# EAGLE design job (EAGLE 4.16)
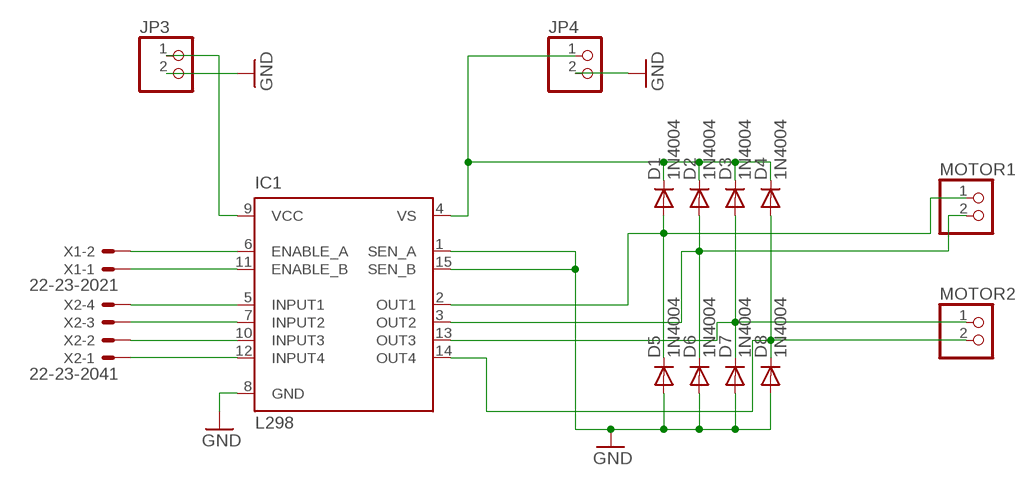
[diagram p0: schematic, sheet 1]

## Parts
D1  1N4004  [DO41-10]
D2  1N4004  [DO41-10]
D3  1N4004  [DO41-10]
D4  1N4004  [DO41-10]
D5  1N4004  [DO41-10]
D6  1N4004  [DO41-10]
D7  1N4004  [DO41-10]
D8  1N4004  [DO41-10]
IC1  L298  [MULTIWATT-15]
JP3  PINHD-1X2  [1X02]
JP4  PINHD-1X2  [1X02]
MOTOR1  PINHD-1X2  [1X02]
MOTOR2  PINHD-1X2  [1X02]
X1  22-23-2021  [22-23-2021]
X2  22-23-2041  [22-23-2041]

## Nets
GND: D5.A D6.A D7.A D8.A IC1.1(SEN_A) IC1.8(GND) IC1.15(SEN_B) JP3.2 JP4.2
N$1: IC1.9(VCC) JP3.1
N$2: D1.A D5.C IC1.2(OUT1) MOTOR1.1
N$3: D2.A D6.C IC1.3(OUT2) MOTOR1.2
N$4: D3.A D7.C IC1.13(OUT3) MOTOR2.1
N$5: D4.A D8.C IC1.14(OUT4) MOTOR2.2
N$6: D1.C D2.C D3.C D4.C IC1.4(VS) JP4.1
N$13: IC1.5(INPUT1) X2.4
N$14: IC1.7(INPUT2) X2.3
N$15: IC1.10(INPUT3) X2.2
N$16: IC1.12(INPUT4) X2.1
N$17: IC1.6(ENABLE_A) X1.2
N$18: IC1.11(ENABLE_B) X1.1

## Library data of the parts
D1-D8 = diode:1N4004: DIODE
IC1 = st-microelectronics:L298: DUAL FULL-BRIDGE DRIVER
JP3 JP4 MOTOR1 MOTOR2 = pinhead:PINHD-1X2: PIN HEADER
X1 = con-molex:22-23-2021: .100" (2.54mm) Center Header - 2 Pin
X2 = con-molex:22-23-2041: .100" (2.54mm) Center Header - 4 Pin

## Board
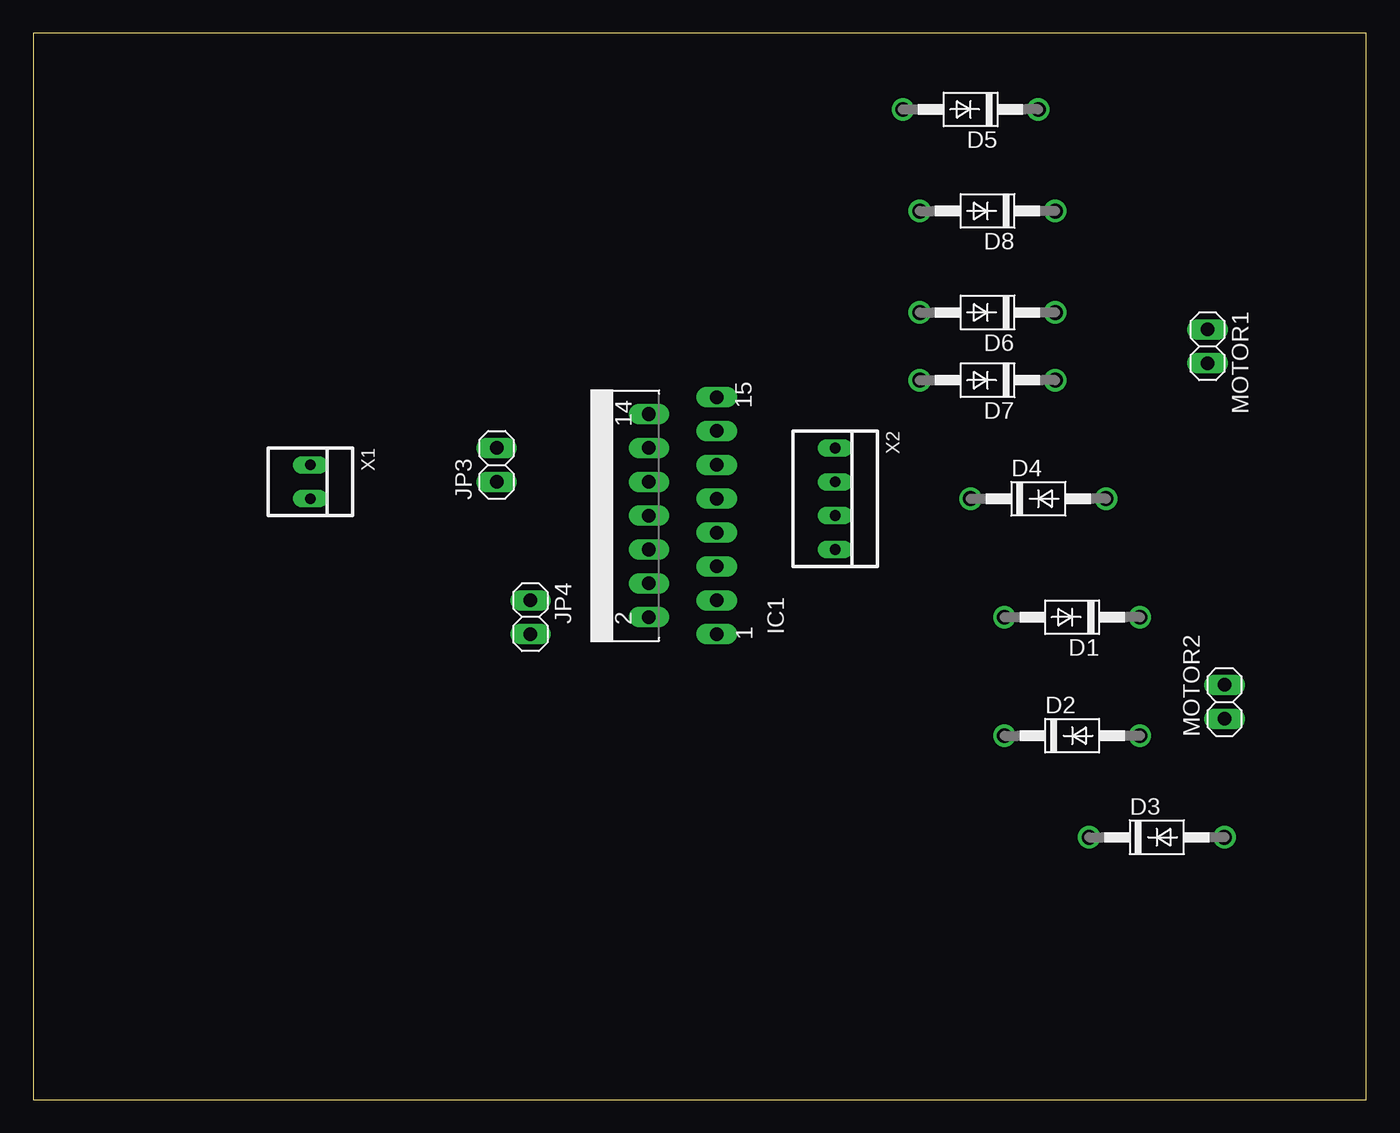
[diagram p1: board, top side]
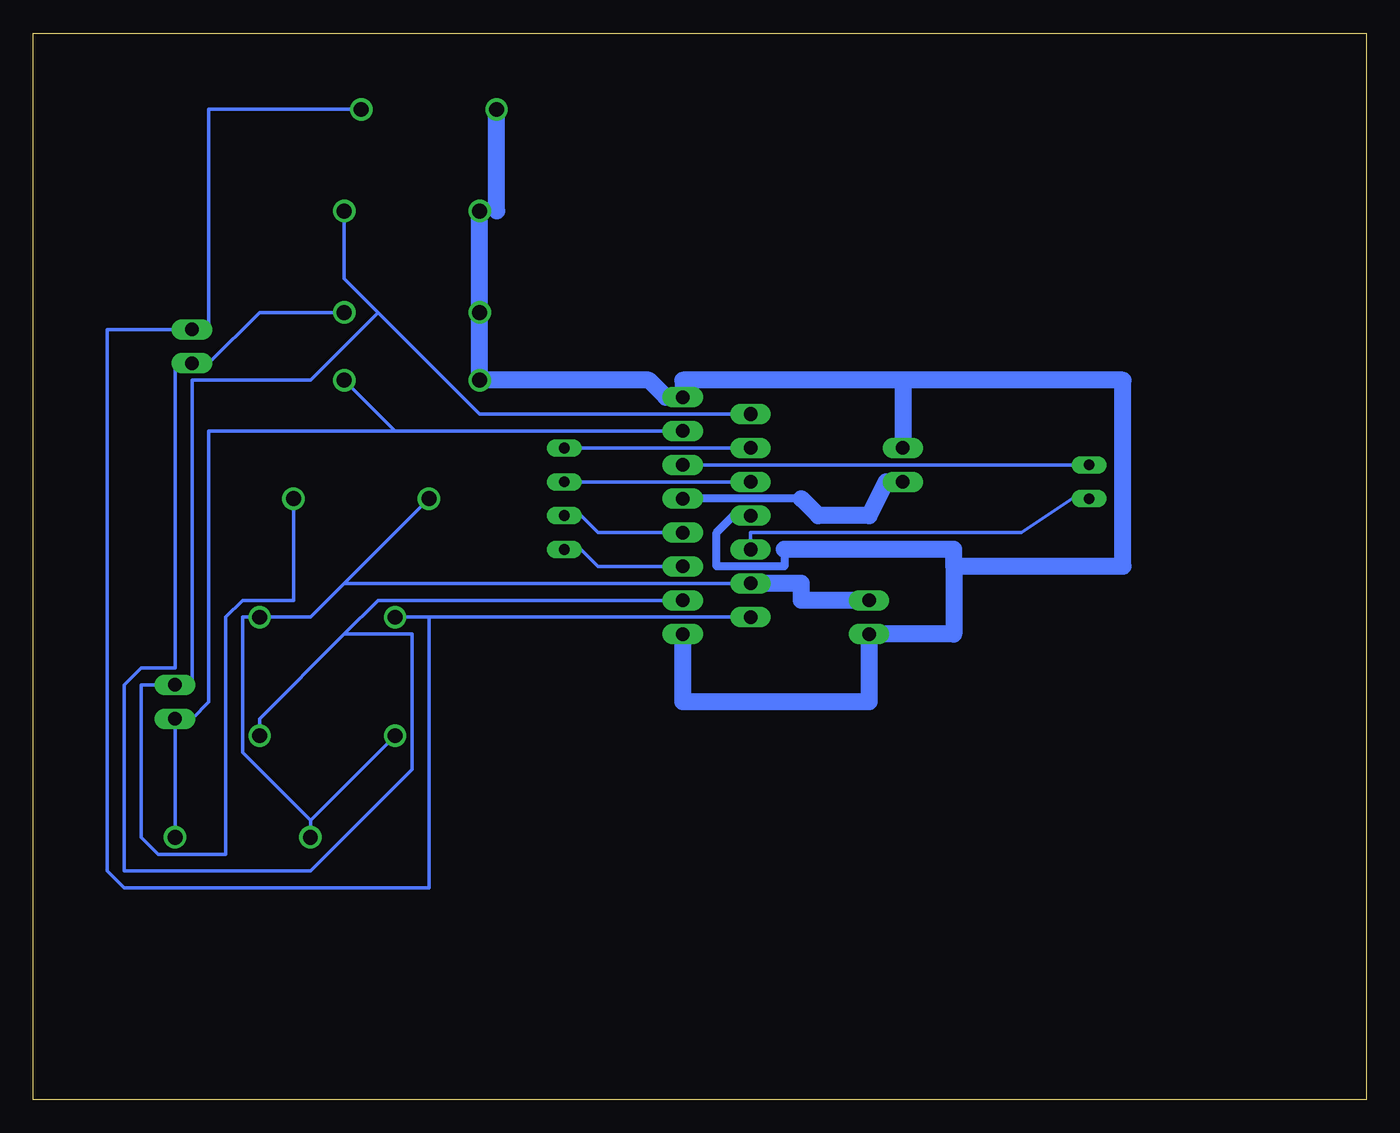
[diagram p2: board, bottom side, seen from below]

Size 100 x 80 mm. Coordinates in mm from the lower left corner, seen from the top.
Outline: 0,0 100,0 100,80 0,80 0,0
Copper layers (1*16): Top 0.035mm / dielectric 1.5mm / Bottom 0.035mm
Design rules "default": minimum track width 10mil, minimum drill 24mil, track to track 8mil, track to pad 8mil, pad to pad 8mil, via to via 8mil, smd to smd 8mil, copper to edge 40mil, drill to drill 8mil, minimum pad ring 10mil, minimum via ring 8mil, stop-mask expansion 4mil, vias tented up to drill 0mil, thermal gap 10mil

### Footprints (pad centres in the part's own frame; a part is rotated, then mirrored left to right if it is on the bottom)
DO41-10 = drill 1.118 round: A 5.08,0; C -5.08,0
MULTIWATT-15 = drill 1.016 long: 1 -8.89,-7.62; 2 -7.62,-2.54; 3 -6.35,-7.62; 4 -5.08,-2.54; 5 -3.81,-7.62; 6 -2.54,-2.54; 7 -1.27,-7.62; 8 0,-2.54; 9 1.27,-7.62; 10 2.54,-2.54; 11 3.81,-7.62; 12 5.08,-2.54; 13 6.35,-7.62; 14 7.62,-2.54; 15 8.89,-7.62
1X02 = drill 1.016 long: 1 -1.27,0; 2 1.27,0
22-23-2021 = drill 0.813 long: 1 -1.27,0; 2 1.27,0
22-23-2041 = drill 0.813 long: 1 -3.81,0; 2 -1.27,0; 3 1.27,0; 4 3.81,0

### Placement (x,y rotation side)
D1  77.94,36.19 180 top
D2  77.94,27.3 0 top
D3  84.29,19.68 0 top
D4  75.4,45.08 0 top
D5  70.32,74.29 180 top
D6  71.59,59.05 180 top
D7  71.59,53.97 180 top
D8  71.59,66.67 180 top
IC1  43.65,43.81 90 top
JP3  34.76,47.62 90 top
JP4  37.3,36.19 270 top
MOTOR1  88.1,56.51 270 top
MOTOR2  89.37,29.84 90 top
X1  20.79,46.35 270 top
X2  60.16,45.08 270 top

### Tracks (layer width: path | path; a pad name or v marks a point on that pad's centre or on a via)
GND
  Bottom 0.254: IC1.15 52.54,52.7 | D8.A 65.24,66.67
  Bottom 0.61: IC1.8 47.46,43.81 48.73,42.54 48.73,40 43.65,40 43.65,41.27
  Bottom 1.27: 52.54,52.7 53.81,53.97 D7.A D6.A D8.A | 65.24,66.67 D5.A | 34.76,53.97 18.25,53.97 18.25,40 30.95,40 | 34.76,53.97 51.27,53.97 IC1.15 | IC1.1 51.27,29.84 37.3,29.84 JP4.2 30.95,34.92 30.95,40 | 30.95,40 30.95,41.27 43.65,41.27 | 34.76,53.97 JP3.2
N$1
  Bottom 0.61: 42.38,45.08 IC1.9
  Bottom 1.27: 42.38,45.08 41.11,43.81 37.3,43.81 36.03,46.35 JP3.1
N$2
  Bottom 0.254: 70.32,36.19 D1.A | IC1.2 70.32,36.19 | D5.C 86.83,74.29 86.83,57.78 MOTOR1.1 94.45,57.78 94.45,17.14 93.18,15.87 70.32,15.87 70.32,36.19
N$3
  Bottom 0.254: D6.C 83.02,59.05 86.83,55.24 MOTOR1.2 89.37,55.24 89.37,32.38 91.91,32.38 93.18,31.11 93.18,17.14 79.21,17.14 71.59,24.76 71.59,34.92 76.67,34.92 | 76.67,34.92 83.02,28.57 D2.A | 76.67,34.92 74.13,37.46 IC1.3
N$4
  Bottom 0.254: D3.A MOTOR2.1 88.1,28.57 86.83,29.84 86.83,50.16 72.86,50.16 | 72.86,50.16 D7.C | IC1.13 72.86,50.16
N$5
  Bottom 0.254: 74.13,59.05 76.67,61.59 D8.C | 74.13,59.05 66.51,51.43 IC1.14 | 74.13,59.05 79.21,53.97 88.1,53.97 88.1,31.11 MOTOR2.2 91.91,31.11 91.91,19.68 90.64,18.41 85.56,18.41 85.56,36.19 84.29,37.46 80.48,37.46 D4.A
N$6
  Bottom 0.254: 79.21,20.95 D2.C | 79.21,20.95 D3.C | 76.67,38.73 79.21,36.19 D1.C 84.29,36.19 84.29,26.03 79.21,20.95 | 76.67,38.73 D4.C | IC1.4 76.67,38.73
  Bottom 1.27: JP4.1 42.38,37.46 42.38,38.73 IC1.4
N$13
  Bottom 0.254: X2.4 58.89,41.27 57.62,40 IC1.5
N$14
  Bottom 0.254: X2.3 58.89,43.81 57.62,42.54 IC1.7
N$15
  Bottom 0.254: IC1.10 X2.2
N$16
  Bottom 0.254: IC1.12 X2.1
N$17
  Bottom 0.254: X1.2 22.06,45.08 25.87,42.54 46.19,42.54 IC1.6
N$18
  Bottom 0.254: X1.1 IC1.11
